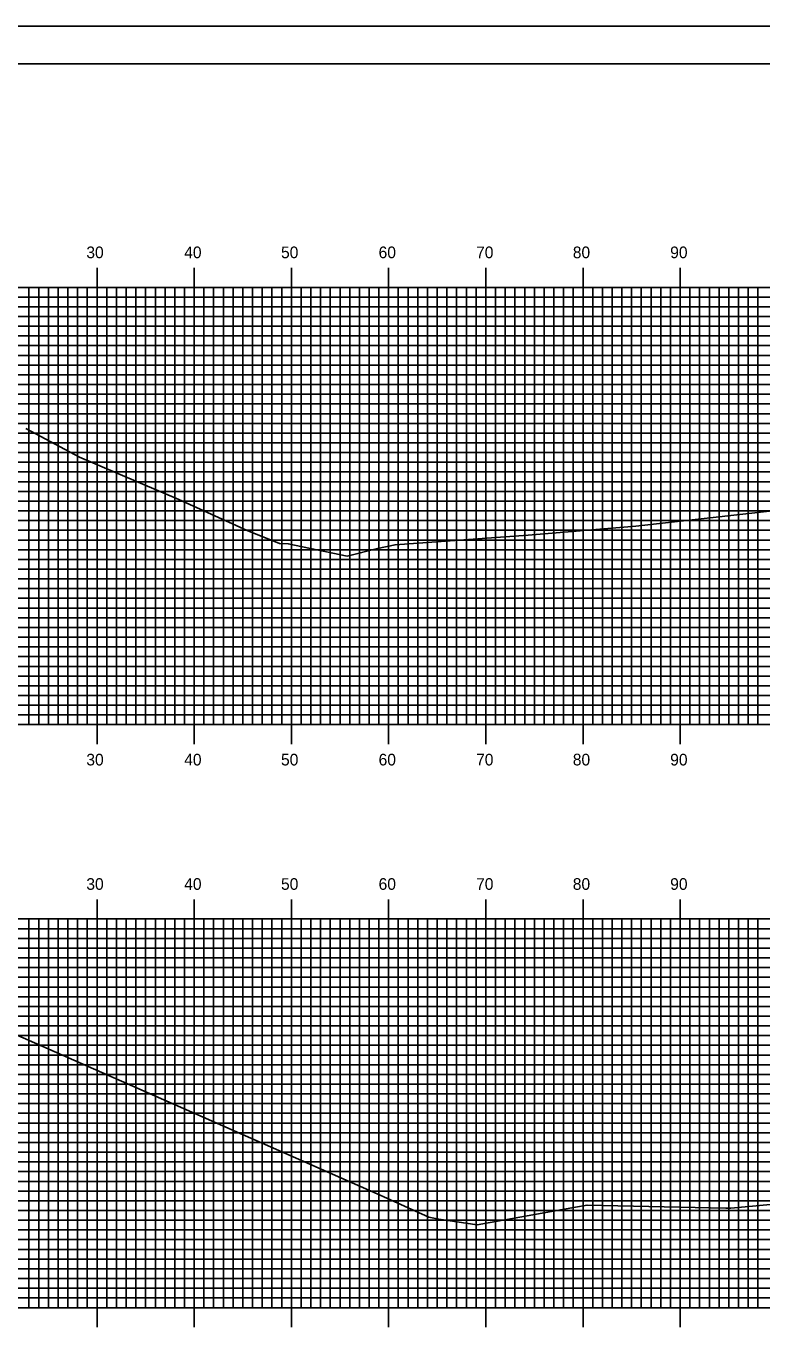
# Model space of a CAD drawing. Extents: x 860258 to 860601, y 364765 to 364985.
# Drawn here: x 860446.6 to 860522.3, y 364850.8 to 364985.2 of the extents above; entities that cross this region are included whole.
import ezdxf

# ---------------------------------------------------------------- set-up
doc = ezdxf.new("R2010")
doc.units = 0
for name, color, linetype in [('BORDER', 7, 'Continuous'), ('H_V ANNOTATION', 7, 'Continuous'), ('MAJOR', 7, 'Continuous'), ('MINOR', 7, 'Continuous'), ('PLOT BOUNDARY', 7, 'Continuous'), ('S_Roadway_Centerline', 7, 'Continuous')]:
    doc.layers.add(name, color=color, linetype=linetype)

msp = doc.modelspace()

# ---------------------------------------------------------------- linework, layer by layer
at = {"layer": 'BORDER'}
msp.add_lwpolyline([(860274.3, 364771.3), (860594.3, 364771.3), (860594.3, 364981.3), (860274.3, 364981.3)], close=True, dxfattribs=at)
at = {"layer": 'MAJOR'}
for p, q in [((860453.9, 364960.31), (860453.9, 364958.3)), ((860463.9, 364960.31), (860463.9, 364958.3)), ((860473.9, 364960.31), (860473.9, 364958.3)), ((860483.9, 364960.31), (860483.9, 364958.3)), ((860493.9, 364960.31), (860493.9, 364958.3)), ((860503.9, 364960.31), (860503.9, 364958.3)), ((860513.9, 364960.31), (860513.9, 364958.3)), ((860283.9, 364958.3), (860563.9, 364958.3)), ((860283.9, 364958.3), (860563.9, 364958.3)), ((860453.9, 364913.3), (860453.9, 364958.3)), ((860463.9, 364913.3), (860463.9, 364958.3)), ((860473.9, 364913.3), (860473.9, 364958.3)), ((860483.9, 364913.3), (860483.9, 364958.3)), ((860493.9, 364913.3), (860493.9, 364958.3)), ((860503.9, 364913.3), (860503.9, 364958.3)), ((860513.9, 364913.3), (860513.9, 364958.3)), ((860283.9, 364953.3), (860563.9, 364953.3)), ((860283.9, 364948.3), (860563.9, 364948.3)), ((860283.9, 364943.3), (860563.9, 364943.3)), ((860283.9, 364938.3), (860563.9, 364938.3)), ((860283.9, 364933.3), (860563.9, 364933.3)), ((860283.9, 364928.3), (860563.9, 364928.3)), ((860283.9, 364923.3), (860563.9, 364923.3)), ((860283.9, 364918.3), (860563.9, 364918.3)), ((860283.9, 364913.3), (860563.9, 364913.3)), ((860283.9, 364913.3), (860563.9, 364913.3)), ((860453.9, 364911.3), (860453.9, 364913.3)), ((860463.9, 364911.3), (860463.9, 364913.3)), ((860473.9, 364911.3), (860473.9, 364913.3)), ((860483.9, 364911.3), (860483.9, 364913.3)), ((860493.9, 364911.3), (860493.9, 364913.3)), ((860503.9, 364911.3), (860503.9, 364913.3)), ((860513.9, 364911.3), (860513.9, 364913.3)), ((860453.9, 364895.31), (860453.9, 364893.3)), ((860463.9, 364895.31), (860463.9, 364893.3)), ((860473.9, 364895.31), (860473.9, 364893.3)), ((860483.9, 364895.31), (860483.9, 364893.3)), ((860493.9, 364895.31), (860493.9, 364893.3)), ((860503.9, 364895.31), (860503.9, 364893.3)), ((860513.9, 364895.31), (860513.9, 364893.3)), ((860283.9, 364893.3), (860563.9, 364893.3)), ((860283.9, 364893.3), (860563.9, 364893.3)), ((860453.9, 364853.3), (860453.9, 364893.3)), ((860463.9, 364853.3), (860463.9, 364893.3)), ((860473.9, 364853.3), (860473.9, 364893.3)), ((860483.9, 364853.3), (860483.9, 364893.3)), ((860493.9, 364853.3), (860493.9, 364893.3)), ((860503.9, 364853.3), (860503.9, 364893.3)), ((860513.9, 364853.3), (860513.9, 364893.3)), ((860283.9, 364888.3), (860563.9, 364888.3)), ((860283.9, 364883.3), (860563.9, 364883.3)), ((860283.9, 364878.3), (860563.9, 364878.3)), ((860283.9, 364873.3), (860563.9, 364873.3)), ((860283.9, 364868.3), (860563.9, 364868.3)), ((860283.9, 364863.3), (860563.9, 364863.3)), ((860283.9, 364858.3), (860563.9, 364858.3)), ((860283.9, 364853.3), (860563.9, 364853.3)), ((860283.9, 364853.3), (860563.9, 364853.3)), ((860453.9, 364851.3), (860453.9, 364853.3)), ((860463.9, 364851.3), (860463.9, 364853.3)), ((860473.9, 364851.3), (860473.9, 364853.3)), ((860483.9, 364851.3), (860483.9, 364853.3)), ((860493.9, 364851.3), (860493.9, 364853.3)), ((860503.9, 364851.3), (860503.9, 364853.3)), ((860513.9, 364851.3), (860513.9, 364853.3))]:
    msp.add_line(p, q, dxfattribs=at)
at = {"layer": 'MINOR'}
for p, q in [((860446.9, 364913.3), (860446.9, 364958.3)), ((860447.9, 364913.3), (860447.9, 364958.3)), ((860448.9, 364913.3), (860448.9, 364958.3)), ((860449.9, 364913.3), (860449.9, 364958.3)), ((860450.9, 364913.3), (860450.9, 364958.3)), ((860451.9, 364913.3), (860451.9, 364958.3)), ((860452.9, 364913.3), (860452.9, 364958.3)), ((860454.9, 364913.3), (860454.9, 364958.3)), ((860455.9, 364913.3), (860455.9, 364958.3)), ((860456.9, 364913.3), (860456.9, 364958.3)), ((860457.9, 364913.3), (860457.9, 364958.3)), ((860458.9, 364913.3), (860458.9, 364958.3)), ((860459.9, 364913.3), (860459.9, 364958.3)), ((860460.9, 364913.3), (860460.9, 364958.3)), ((860461.9, 364913.3), (860461.9, 364958.3)), ((860462.9, 364913.3), (860462.9, 364958.3)), ((860464.9, 364913.3), (860464.9, 364958.3)), ((860465.9, 364913.3), (860465.9, 364958.3)), ((860466.9, 364913.3), (860466.9, 364958.3)), ((860467.9, 364913.3), (860467.9, 364958.3)), ((860468.9, 364913.3), (860468.9, 364958.3)), ((860469.9, 364913.3), (860469.9, 364958.3)), ((860470.9, 364913.3), (860470.9, 364958.3)), ((860471.9, 364913.3), (860471.9, 364958.3)), ((860472.9, 364913.3), (860472.9, 364958.3)), ((860474.9, 364913.3), (860474.9, 364958.3)), ((860475.9, 364913.3), (860475.9, 364958.3)), ((860476.9, 364913.3), (860476.9, 364958.3)), ((860477.9, 364913.3), (860477.9, 364958.3)), ((860478.9, 364913.3), (860478.9, 364958.3)), ((860479.9, 364913.3), (860479.9, 364958.3)), ((860480.9, 364913.3), (860480.9, 364958.3)), ((860481.9, 364913.3), (860481.9, 364958.3)), ((860482.9, 364913.3), (860482.9, 364958.3)), ((860484.9, 364913.3), (860484.9, 364958.3)), ((860485.9, 364913.3), (860485.9, 364958.3)), ((860486.9, 364913.3), (860486.9, 364958.3)), ((860487.9, 364913.3), (860487.9, 364958.3)), ((860488.9, 364913.3), (860488.9, 364958.3)), ((860489.9, 364913.3), (860489.9, 364958.3)), ((860490.9, 364913.3), (860490.9, 364958.3)), ((860491.9, 364913.3), (860491.9, 364958.3)), ((860492.9, 364913.3), (860492.9, 364958.3)), ((860494.9, 364913.3), (860494.9, 364958.3)), ((860495.9, 364913.3), (860495.9, 364958.3)), ((860496.9, 364913.3), (860496.9, 364958.3)), ((860497.9, 364913.3), (860497.9, 364958.3)), ((860498.9, 364913.3), (860498.9, 364958.3)), ((860499.9, 364913.3), (860499.9, 364958.3)), ((860500.9, 364913.3), (860500.9, 364958.3)), ((860501.9, 364913.3), (860501.9, 364958.3)), ((860502.9, 364913.3), (860502.9, 364958.3)), ((860504.9, 364913.3), (860504.9, 364958.3)), ((860505.9, 364913.3), (860505.9, 364958.3)), ((860506.9, 364913.3), (860506.9, 364958.3)), ((860507.9, 364913.3), (860507.9, 364958.3)), ((860508.9, 364913.3), (860508.9, 364958.3)), ((860509.9, 364913.3), (860509.9, 364958.3)), ((860510.9, 364913.3), (860510.9, 364958.3)), ((860511.9, 364913.3), (860511.9, 364958.3)), ((860512.9, 364913.3), (860512.9, 364958.3)), ((860514.9, 364913.3), (860514.9, 364958.3)), ((860515.9, 364913.3), (860515.9, 364958.3)), ((860516.9, 364913.3), (860516.9, 364958.3)), ((860517.9, 364913.3), (860517.9, 364958.3)), ((860518.9, 364913.3), (860518.9, 364958.3)), ((860519.9, 364913.3), (860519.9, 364958.3)), ((860520.9, 364913.3), (860520.9, 364958.3)), ((860521.9, 364913.3), (860521.9, 364958.3)), ((860283.9, 364957.3), (860563.9, 364957.3)), ((860283.9, 364956.3), (860563.9, 364956.3)), ((860283.9, 364955.3), (860563.9, 364955.3)), ((860283.9, 364954.3), (860563.9, 364954.3)), ((860283.9, 364952.3), (860563.9, 364952.3)), ((860283.9, 364951.3), (860563.9, 364951.3)), ((860283.9, 364950.3), (860563.9, 364950.3)), ((860283.9, 364949.3), (860563.9, 364949.3)), ((860283.9, 364947.3), (860563.9, 364947.3)), ((860283.9, 364946.3), (860563.9, 364946.3)), ((860283.9, 364945.3), (860563.9, 364945.3)), ((860283.9, 364944.3), (860563.9, 364944.3)), ((860283.9, 364942.3), (860563.9, 364942.3)), ((860283.9, 364941.3), (860563.9, 364941.3)), ((860283.9, 364940.3), (860563.9, 364940.3)), ((860283.9, 364939.3), (860563.9, 364939.3)), ((860283.9, 364937.3), (860563.9, 364937.3)), ((860283.9, 364936.3), (860563.9, 364936.3)), ((860283.9, 364935.3), (860563.9, 364935.3)), ((860283.9, 364934.3), (860563.9, 364934.3)), ((860283.9, 364932.3), (860563.9, 364932.3)), ((860283.9, 364931.3), (860563.9, 364931.3)), ((860283.9, 364930.3), (860563.9, 364930.3)), ((860283.9, 364929.3), (860563.9, 364929.3)), ((860283.9, 364927.3), (860563.9, 364927.3)), ((860283.9, 364926.3), (860563.9, 364926.3)), ((860283.9, 364925.3), (860563.9, 364925.3)), ((860283.9, 364924.3), (860563.9, 364924.3)), ((860283.9, 364922.3), (860563.9, 364922.3)), ((860283.9, 364921.3), (860563.9, 364921.3)), ((860283.9, 364920.3), (860563.9, 364920.3)), ((860283.9, 364919.3), (860563.9, 364919.3)), ((860283.9, 364917.3), (860563.9, 364917.3)), ((860283.9, 364916.3), (860563.9, 364916.3)), ((860283.9, 364915.3), (860563.9, 364915.3)), ((860283.9, 364914.3), (860563.9, 364914.3)), ((860283.9, 364892.3), (860563.9, 364892.3)), ((860446.9, 364853.3), (860446.9, 364893.3)), ((860447.9, 364853.3), (860447.9, 364893.3)), ((860448.9, 364853.3), (860448.9, 364893.3)), ((860449.9, 364853.3), (860449.9, 364893.3)), ((860450.9, 364853.3), (860450.9, 364893.3)), ((860451.9, 364853.3), (860451.9, 364893.3)), ((860452.9, 364853.3), (860452.9, 364893.3)), ((860454.9, 364853.3), (860454.9, 364893.3)), ((860455.9, 364853.3), (860455.9, 364893.3)), ((860456.9, 364853.3), (860456.9, 364893.3)), ((860457.9, 364853.3), (860457.9, 364893.3)), ((860458.9, 364853.3), (860458.9, 364893.3)), ((860459.9, 364853.3), (860459.9, 364893.3)), ((860460.9, 364853.3), (860460.9, 364893.3)), ((860461.9, 364853.3), (860461.9, 364893.3)), ((860462.9, 364853.3), (860462.9, 364893.3)), ((860464.9, 364853.3), (860464.9, 364893.3)), ((860465.9, 364853.3), (860465.9, 364893.3)), ((860466.9, 364853.3), (860466.9, 364893.3)), ((860467.9, 364853.3), (860467.9, 364893.3)), ((860468.9, 364853.3), (860468.9, 364893.3)), ((860469.9, 364853.3), (860469.9, 364893.3)), ((860470.9, 364853.3), (860470.9, 364893.3)), ((860471.9, 364853.3), (860471.9, 364893.3)), ((860472.9, 364853.3), (860472.9, 364893.3)), ((860474.9, 364853.3), (860474.9, 364893.3)), ((860475.9, 364853.3), (860475.9, 364893.3)), ((860476.9, 364853.3), (860476.9, 364893.3)), ((860477.9, 364853.3), (860477.9, 364893.3)), ((860478.9, 364853.3), (860478.9, 364893.3)), ((860479.9, 364853.3), (860479.9, 364893.3)), ((860480.9, 364853.3), (860480.9, 364893.3)), ((860481.9, 364853.3), (860481.9, 364893.3)), ((860482.9, 364853.3), (860482.9, 364893.3)), ((860484.9, 364853.3), (860484.9, 364893.3)), ((860485.9, 364853.3), (860485.9, 364893.3)), ((860486.9, 364853.3), (860486.9, 364893.3)), ((860487.9, 364853.3), (860487.9, 364893.3)), ((860488.9, 364853.3), (860488.9, 364893.3)), ((860489.9, 364853.3), (860489.9, 364893.3)), ((860490.9, 364853.3), (860490.9, 364893.3)), ((860491.9, 364853.3), (860491.9, 364893.3)), ((860492.9, 364853.3), (860492.9, 364893.3)), ((860494.9, 364853.3), (860494.9, 364893.3)), ((860495.9, 364853.3), (860495.9, 364893.3)), ((860496.9, 364853.3), (860496.9, 364893.3)), ((860497.9, 364853.3), (860497.9, 364893.3)), ((860498.9, 364853.3), (860498.9, 364893.3)), ((860499.9, 364853.3), (860499.9, 364893.3)), ((860500.9, 364853.3), (860500.9, 364893.3)), ((860501.9, 364853.3), (860501.9, 364893.3)), ((860502.9, 364853.3), (860502.9, 364893.3)), ((860504.9, 364853.3), (860504.9, 364893.3)), ((860505.9, 364853.3), (860505.9, 364893.3)), ((860506.9, 364853.3), (860506.9, 364893.3)), ((860507.9, 364853.3), (860507.9, 364893.3)), ((860508.9, 364853.3), (860508.9, 364893.3)), ((860509.9, 364853.3), (860509.9, 364893.3)), ((860510.9, 364853.3), (860510.9, 364893.3)), ((860511.9, 364853.3), (860511.9, 364893.3)), ((860512.9, 364853.3), (860512.9, 364893.3)), ((860514.9, 364853.3), (860514.9, 364893.3)), ((860515.9, 364853.3), (860515.9, 364893.3)), ((860516.9, 364853.3), (860516.9, 364893.3)), ((860517.9, 364853.3), (860517.9, 364893.3)), ((860518.9, 364853.3), (860518.9, 364893.3)), ((860519.9, 364853.3), (860519.9, 364893.3)), ((860520.9, 364853.3), (860520.9, 364893.3)), ((860521.9, 364853.3), (860521.9, 364893.3)), ((860283.9, 364891.3), (860563.9, 364891.3)), ((860283.9, 364890.3), (860563.9, 364890.3)), ((860283.9, 364889.3), (860563.9, 364889.3)), ((860283.9, 364887.3), (860563.9, 364887.3)), ((860283.9, 364886.3), (860563.9, 364886.3)), ((860283.9, 364885.3), (860563.9, 364885.3)), ((860283.9, 364884.3), (860563.9, 364884.3)), ((860283.9, 364882.3), (860563.9, 364882.3)), ((860283.9, 364881.3), (860563.9, 364881.3)), ((860283.9, 364880.3), (860563.9, 364880.3)), ((860283.9, 364879.3), (860563.9, 364879.3)), ((860283.9, 364877.3), (860563.9, 364877.3)), ((860283.9, 364876.3), (860563.9, 364876.3)), ((860283.9, 364875.3), (860563.9, 364875.3)), ((860283.9, 364874.3), (860563.9, 364874.3)), ((860283.9, 364872.3), (860563.9, 364872.3)), ((860283.9, 364871.3), (860563.9, 364871.3)), ((860283.9, 364870.3), (860563.9, 364870.3)), ((860283.9, 364869.3), (860563.9, 364869.3)), ((860283.9, 364867.3), (860563.9, 364867.3)), ((860283.9, 364866.3), (860563.9, 364866.3)), ((860283.9, 364865.3), (860563.9, 364865.3)), ((860283.9, 364864.3), (860563.9, 364864.3)), ((860283.9, 364862.3), (860563.9, 364862.3)), ((860283.9, 364861.3), (860563.9, 364861.3)), ((860283.9, 364860.3), (860563.9, 364860.3)), ((860283.9, 364859.3), (860563.9, 364859.3)), ((860283.9, 364857.3), (860563.9, 364857.3)), ((860283.9, 364856.3), (860563.9, 364856.3)), ((860283.9, 364855.3), (860563.9, 364855.3)), ((860283.9, 364854.3), (860563.9, 364854.3))]:
    msp.add_line(p, q, dxfattribs=at)
at = {"layer": 'PLOT BOUNDARY'}
msp.add_lwpolyline([(860258.11, 364765.18), (860598.11, 364765.18), (860598.11, 364985.18), (860258.11, 364985.18)], close=True, dxfattribs=at)
at = {"layer": 'S_Roadway_Centerline'}
for points in [[(860446.58, 364943.76), (860452.1, 364940.82), (860462.33, 364936.47), (860469.34, 364933.29), (860472.69, 364931.93), (860473.57, 364931.92), (860479.63, 364930.64), (860482.76, 364931.42), (860484.56, 364931.81), (860498.25, 364932.79), (860509.33, 364933.74), (860523.71, 364935.34), (860536.17, 364937.13), (860538.13, 364937.35), (860547.8, 364937.69), (860552.56, 364937.79), (860553.61, 364937.62), (860563.9, 364936.19)], [(860432.09, 364887.3), (860483.02, 364864.87), (860488.04, 364862.6), (860489.08, 364862.42), (860493.01, 364861.83), (860503.14, 364863.66), (860504.32, 364863.86), (860518.6, 364863.54), (860519.1, 364863.54), (860533.18, 364864.85), (860534.62, 364865.01), (860538.09, 364865.36), (860552.94, 364866.16), (860563.9, 364867.17)]]:
    msp.add_lwpolyline(points, dxfattribs=at)

# ---------------------------------------------------------------- texts
at = {"layer": 'H_V ANNOTATION'}
for s, p in [('30', (860452.8, 364961.3)), ('40', (860462.87, 364961.3)), ('50', (860472.83, 364961.3)), ('60', (860482.87, 364961.3)), ('70', (860492.9, 364961.3)), ('80', (860502.85, 364961.3)), ('90', (860512.87, 364961.3)), ('30', (860452.8, 364909.1)), ('40', (860462.87, 364909.1)), ('50', (860472.83, 364909.1)), ('60', (860482.87, 364909.1)), ('70', (860492.9, 364909.1)), ('80', (860502.85, 364909.1)), ('90', (860512.87, 364909.1)), ('30', (860452.8, 364896.3)), ('40', (860462.87, 364896.3)), ('50', (860472.83, 364896.3)), ('60', (860482.87, 364896.3)), ('70', (860492.9, 364896.3)), ('80', (860502.85, 364896.3)), ('90', (860512.87, 364896.3))]:
    msp.add_text(s, height=1.2, dxfattribs=at).set_placement(p)

doc.saveas('drawing.dxf')
